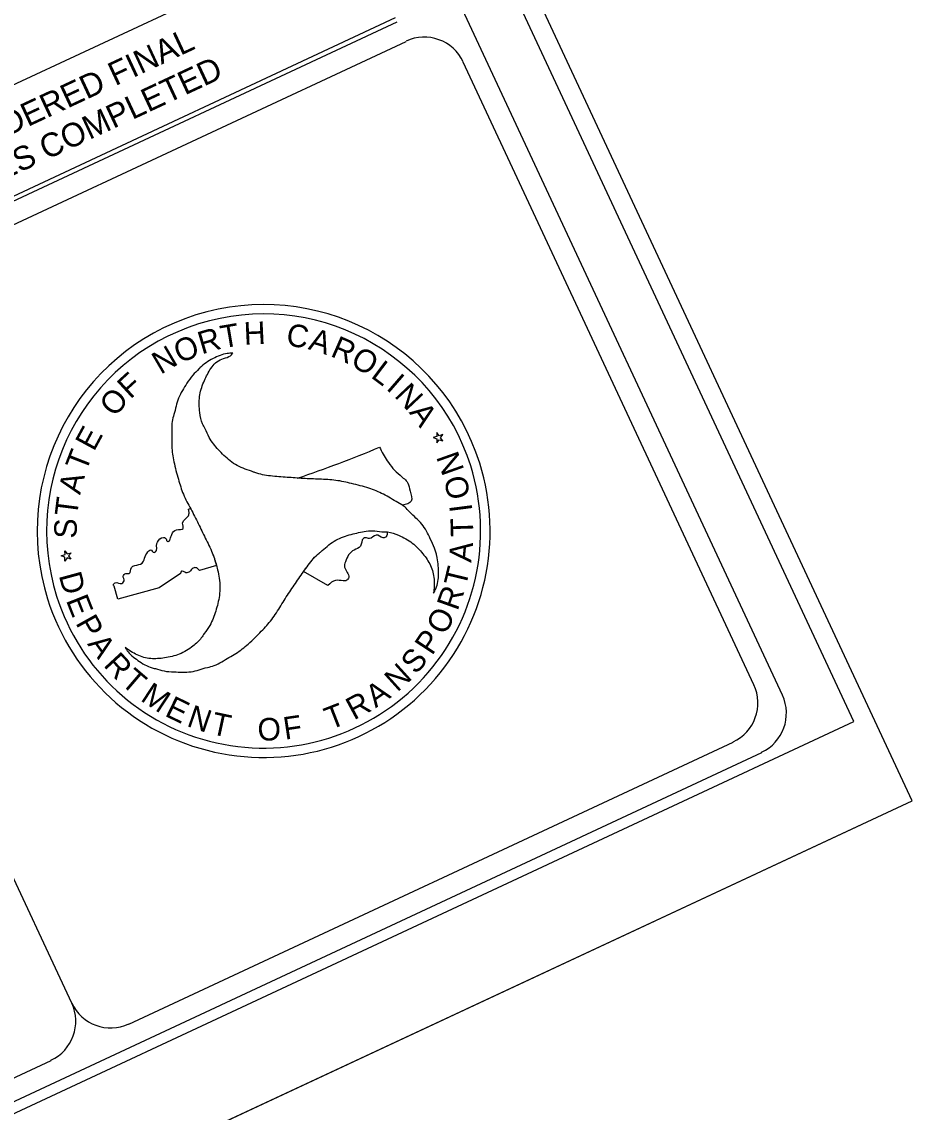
# Model space of a CAD drawing. Extents: x 2318983 to 2324558, y 920396 to 924651.
# Drawn here: x 2323820 to 2324317, y 922085 to 922694 of the extents above; entities that cross this region are included whole.
import ezdxf

# ---------------------------------------------------------------- set-up
doc = ezdxf.new("R2010")
doc.units = 0
for name, color, linetype in [('Sheet Cutting Line CELL', 7, 'Continuous'), ('Sheet Plot Border Inside CELL', 7, 'Continuous'), ('Sheet Plot Border Outside CELL', 7, 'Continuous'), ('Sheet Sticker Exception Certification CELL', 7, 'Continuous'), ('Sheet Title CELL', 7, 'Continuous')]:
    doc.layers.add(name, color=color, linetype=linetype)

msp = doc.modelspace()

# ---------------------------------------------------------------- linework, layer by layer
at = {"layer": 'Sheet Cutting Line CELL'}
msp.add_line((2320654.8, 920549.69), (2324317.18, 922258.94), dxfattribs=at)
at = {"layer": 'Sheet Plot Border Inside CELL'}
msp.add_lwpolyline([(2320660.3, 920611.69), (2324284.61, 922303.17), (2323213.7, 924597.81), (2319589.38, 922906.33)], close=True, dxfattribs=at)
at = {"layer": 'Sheet Plot Border Outside CELL'}
msp.add_lwpolyline([(2323200.7, 924651.2), (2319538.32, 922941.96), (2320654.8, 920549.69), (2324317.18, 922258.94)], close=True, dxfattribs=at)
at = {"layer": 'Sheet Sticker Exception Certification CELL'}
for p, q in [((2323569.44, 922544.31), (2324004.48, 922747.34)), ((2324028.34, 922696.24), (2323593.29, 922493.2))]:
    msp.add_line(p, q, dxfattribs=at)
at = {"layer": 'Sheet Title CELL'}
for p, q in [((2320941.13, 921252.76), (2324029.36, 922694.05)), ((2323696.84, 922525.62), (2324034.43, 922683.17)), ((2323937.57, 922509.24), (2323937.43, 922508.92)), ((2323937.57, 922509.24), (2323937.43, 922508.92)), ((2323847.64, 922145.75), (2323685.24, 922493.72)), ((2324051.56, 922462.42), (2324049.49, 922461.77)), ((2324049.49, 922461.77), (2324051.59, 922461.09)), ((2324051.6, 922464.56), (2324051.56, 922462.42)), ((2324051.59, 922461.09), (2324051.61, 922458.9)), ((2324052.92, 922462.85), (2324051.6, 922464.56)), ((2324054.94, 922463.56), (2324052.92, 922462.85)), ((2324053.66, 922461.75), (2324054.94, 922463.56)), ((2324054.9, 922459.93), (2324053.66, 922461.75)), ((2324051.61, 922458.9), (2324052.84, 922460.62)), ((2324052.84, 922460.62), (2324054.9, 922459.93)), ((2324075.5, 922447.54), (2324075.5, 922447.54)), ((2323973.77, 922439.16), (2323973.77, 922439.16)), ((2323841.73, 922395.76), (2323843.85, 922396.42)), ((2323843.81, 922395.04), (2323841.73, 922395.76)), ((2323843.85, 922396.42), (2323843.81, 922398.53)), ((2323843.81, 922398.53), (2323845.13, 922396.83)), ((2323843.83, 922392.84), (2323843.81, 922395.04)), ((2323845.05, 922394.6), (2323843.83, 922392.84)), ((2323847.16, 922393.89), (2323845.05, 922394.6)), ((2323845.13, 922396.83), (2323847.21, 922397.48)), ((2323847.21, 922397.48), (2323845.88, 922395.69)), ((2323845.88, 922395.69), (2323847.16, 922393.89)), ((2323928.55, 922390.41), (2323918.97, 922387.52)), ((2323908.41, 922385.85), (2323896.49, 922377.86)), ((2323990.73, 922379.16), (2323977.16, 922386.97)), ((2323977.16, 922386.97), (2323977.16, 922386.97)), ((2323873.32, 922371.53), (2323871.29, 922378.87)), ((2323896.49, 922377.86), (2323873.32, 922371.53))]:
    msp.add_line(p, q, dxfattribs=at)
for points in [[(2324244.68, 922317.81), (2323199.25, 924557.83)], [(2324228.73, 922323.61), (2324066.33, 922671.57)], [(2323879.55, 922134.15), (2324217.13, 922291.71)], [(2321014.38, 920783.69), (2324233.09, 922285.88)], [(2323401.58, 921911.08), (2323836.05, 922113.85)]]:
    msp.add_lwpolyline(points, dxfattribs=at)
for centre, radius, start, end in [((2324044.55, 922661.53), 24, 25.01869, 115.01869), ((2323954.82, 922409.6), 126.52, 17.43983, 197.43983), ((2323954.82, 922409.6), 121.25, 17.43983, 197.43983), ((2323761.47, 923071.55), 667.07, 288.55737, 292.76338), ((2323954.82, 922409.6), 126.52, 197.43983, 17.43983), ((2323954.82, 922409.6), 121.25, 197.43983, 17.43983), ((2323761.47, 923071.55), 667.07, 283.11832, 283.21791), ((2324206.95, 922313.56), 24, 295.01869, 25.01869), ((2324222.89, 922307.76), 24, 295.01869, 25.01869), ((2323825.84, 922135.73), 24, 295.01869, 25.01869), ((2323869.34, 922156.03), 24, 205.01869, 295.01869)]:
    msp.add_arc(centre, radius, start, end, dxfattribs=at)
for points in [[(2323937.43, 922508.92), (2323934.49, 922508.78), (2323926.58, 922505.94), (2323919.24, 922500.77), (2323918.65, 922500.15), (2323915.24, 922496.72), (2323911.93, 922492.14), (2323907.32, 922483.89), (2323904.71, 922474.7), (2323903.73, 922470.81), (2323903.52, 922466.35), (2323903.51, 922456.99), (2323904.7, 922448.32), (2323907.19, 922438.53), (2323909.98, 922430.13), (2323914.09, 922421.95), (2323918.32, 922413.73), (2323922.22, 922405.68), (2323926.14, 922397.35), (2323928.88, 922388.74), (2323929.08, 922387.98), (2323930.43, 922378.3), (2323929.24, 922369.08), (2323926.57, 922360.82), (2323924.72, 922356.82), (2323921.67, 922352.4), (2323919.95, 922349.85), (2323915.35, 922345.34), (2323907.7, 922340.82), (2323899.46, 922338.74), (2323891.74, 922338.32), (2323884.17, 922340.38), (2323877.38, 922344.62)], [(2324049.76, 922374.83), (2324051.01, 922377.35), (2324052.57, 922385.66), (2324051.76, 922394.6), (2324051.61, 922395.46), (2324050.23, 922400.1), (2324047.93, 922405.31), (2324043.17, 922413.44), (2324036.44, 922420.21), (2324033.62, 922423.06), (2324029.79, 922425.51), (2324021.72, 922430.17), (2324013.64, 922433.49), (2324003.91, 922436.17), (2323995.24, 922437.89), (2323986.03, 922438.54), (2323976.86, 922438.96), (2323968.01, 922439.6), (2323958.69, 922440.36), (2323949.95, 922442.29), (2323949.2, 922442.57), (2323940.03, 922446.21), (2323932.67, 922451.88), (2323926.81, 922458.26), (2323924.42, 922461.87), (2323922.1, 922466.76), (2323920.64, 922469.52), (2323919.16, 922475.74), (2323919.02, 922484.7), (2323921.32, 922492.77), (2323924.85, 922499.66), (2323930.46, 922505.2), (2323937.43, 922508.92), (2323937.57, 922509.24)], [(2324019.57, 922456.42), (2324023.81, 922448.91), (2324031.01, 922440.76), (2324035.36, 922436.42), (2324036.69, 922431.93), (2324037.33, 922426.27), (2324032.35, 922424.12)], [(2324032.32, 922424.07), (2324029.79, 922425.51), (2324021.72, 922430.17), (2324013.64, 922433.49), (2324003.91, 922436.17), (2323995.24, 922437.89), (2323986.03, 922438.54), (2323976.86, 922438.96), (2323973.77, 922439.16)], [(2323871.29, 922378.87), (2323870.83, 922379.47), (2323871.8, 922380.64), (2323875.64, 922380.31), (2323876.89, 922382.32), (2323876.36, 922383.76), (2323877.26, 922385.65), (2323879.73, 922385.92), (2323881, 922389.27), (2323882.78, 922390.34), (2323886.86, 922391.62), (2323890.16, 922398), (2323892.11, 922398.93), (2323893.02, 922397.8), (2323894.35, 922397.94), (2323895.17, 922402.6), (2323895.52, 922403.34), (2323898.84, 922406.04), (2323900.07, 922405.63), (2323900.92, 922403.94), (2323901.57, 922403.75), (2323902.54, 922405.03), (2323903.54, 922407.71), (2323906.15, 922410.3), (2323909.83, 922410.98), (2323909.53, 922414.07), (2323912.8, 922418.16), (2323913.13, 922420.11), (2323912.8, 922421.9)], [(2323913.98, 922422.15), (2323914.09, 922421.95), (2323918.32, 922413.73), (2323922.22, 922405.68), (2323926.14, 922397.35), (2323928.52, 922390.4)], [(2323877.38, 922344.62), (2323879.09, 922342.17), (2323885.48, 922336.71), (2323893.6, 922332.89), (2323894.39, 922332.74), (2323899.16, 922331.45), (2323904.75, 922330.93), (2323914.24, 922331), (2323923.39, 922333.4), (2323927.27, 922334.43), (2323931.43, 922336.6), (2323939.33, 922341.2), (2323946.25, 922346.48), (2323953.52, 922353.6), (2323959.32, 922360.18), (2323964.44, 922367.88), (2323969.38, 922375.68), (2323974.46, 922383.05), (2323979.76, 922390.58), (2323985.78, 922397.3), (2323986.5, 922397.88), (2323994.2, 922403.92), (2324002.68, 922407.45), (2324011.06, 922409.29), (2324015.6, 922409.74), (2324020.86, 922409.15), (2324024.06, 922409.09), (2324030.17, 922407.28), (2324037.87, 922402.9), (2324043.77, 922396.89), (2324048.03, 922390.33), (2324050.02, 922382.74), (2324049.76, 922374.83)], [(2323977.16, 922386.97), (2323979.76, 922390.58), (2323985.78, 922397.3), (2323986.5, 922397.88), (2323994.2, 922403.92), (2324002.68, 922407.45), (2324011.06, 922409.29), (2324015.6, 922409.74), (2324020.86, 922409.15), (2324023.83, 922409.06)], [(2324023.81, 922409.01), (2324023.36, 922406.55), (2324021.58, 922405.84), (2324017.6, 922407.38), (2324013.95, 922405.36), (2324011.83, 922405.84), (2324010.64, 922405.5), (2324008.93, 922401.08), (2324005.33, 922399), (2324000.52, 922392.42), (2324000.08, 922389.33), (2324002.36, 922383.68), (2324001.18, 922382.06), (2323999.23, 922381.76), (2323994.9, 922382.05), (2323990.73, 922379.16)], [(2323918.97, 922387.52), (2323917.49, 922388.98), (2323915.46, 922388.93), (2323913.37, 922386.82), (2323911.44, 922386.33), (2323908.89, 922387.18), (2323908.41, 922385.85)]]:
    msp.add_spline(points, degree=3, dxfattribs=at)

# ---------------------------------------------------------------- texts
at = {"layer": 'Sheet Sticker Exception Certification CELL'}
for s, p in [('DOCUMENT NOT CONSIDERED FINAL', (2323625.77, 922543.19)), ('UNLESS ALL SIGNATURES COMPLETED', (2323623.67, 922518.91))]:
    msp.add_text(s, height=13.2, rotation=25.01869, dxfattribs=at).set_placement(p)
at = {"layer": 'Sheet Title CELL'}
for s, height, rotation, p in [('R', 12.62, 16.31556, (2323920.23, 922508.23)), ('T', 12.65, 9.66593, (2323931.82, 922511.64)), ('H', 12.6, 2.58121, (2323944.01, 922513.62)), ('C', 12.58, 350.23886, (2323966.85, 922513.48)), ('A', 12.61, 342.74183, (2323979.26, 922511.29)), ('O', 12.65, 22.92549, (2323907.95, 922503.04)), ('R', 12.6, 336.37789, (2323991.62, 922507.47)), ('N', 12.62, 30.4236, (2323897.28, 922496.85)), ('O', 12.64, 329.25828, (2324002.66, 922502.6)), ('L', 12.58, 323.02461, (2324014.21, 922495.74)), ('F', 12.64, 42.51054, (2323880.31, 922482.92)), ('I', 12.63, 319.03526, (2324022.78, 922488.99)), ('N', 12.61, 313.33516, (2324027.37, 922484.89)), ('O', 12.63, 49.65738, (2323871.62, 922472.8)), ('A', 12.62, 305.90318, (2324035.8, 922475.83)), ('E', 12.57, 61.59676, (2323860.02, 922453.66)), ('T', 12.59, 68.71239, (2323855.49, 922442.18)), ('N', 12.62, 109.64796, (2324067.05, 922443.78)), ('A', 12.66, 75.76761, (2323852.27, 922429.53)), ('O', 12.57, 102.39994, (2324070.46, 922428.93)), ('T', 12.64, 82.81992, (2323850.57, 922417.32)), ('I', 12.65, 97.26431, (2324071.56, 922420.91)), ('S', 12.6, 89.19608, (2323850.37, 922405.31)), ('T', 12.6, 91.61441, (2324072.03, 922406.67)), ('A', 12.64, 84.52998, (2324070.77, 922391.77)), ('T', 12.57, 76.44294, (2324067.65, 922377.82)), ('D', 12.62, 285.29282, (2323840.29, 922384.85)), ('R', 12.64, 70.34315, (2324063.11, 922364.6)), ('E', 12.56, 291.58071, (2323844.23, 922370.92)), ('O', 12.64, 63.15404, (2324056.32, 922350.95)), ('P', 12.62, 299.11311, (2323849.5, 922358.26)), ('P', 12.61, 56.46205, (2324048.94, 922339.63)), ('A', 12.6, 305.70568, (2323856.07, 922346.49)), ('R', 12.61, 312.77432, (2323864.92, 922334.45)), ('S', 12.56, 49.2702, (2324039.9, 922329.01)), ('T', 12.6, 319.42485, (2323874.47, 922324.33)), ('N', 12.58, 42.05973, (2324029.48, 922319.25)), ('M', 12.58, 326.65989, (2323885.49, 922315.17)), ('A', 12.58, 35.0281, (2324017.41, 922310.5)), ('E', 12.58, 334.12666, (2323899.04, 922306.57)), ('R', 12.62, 28.27497, (2324005.23, 922303.73)), ('N', 12.64, 341.09821, (2323911.35, 922300.77)), ('T', 12.6, 347.94021, (2323924.87, 922296.29)), ('T', 12.57, 21.31835, (2323991.97, 922298.39)), ('O', 12.61, 1.24389, (2323951.51, 922292.44)), ('F', 12.6, 8.40912, (2323966.75, 922292.98))]:
    msp.add_text(s, height=height, rotation=rotation, dxfattribs=at).set_placement(p)

doc.saveas('drawing.dxf')
